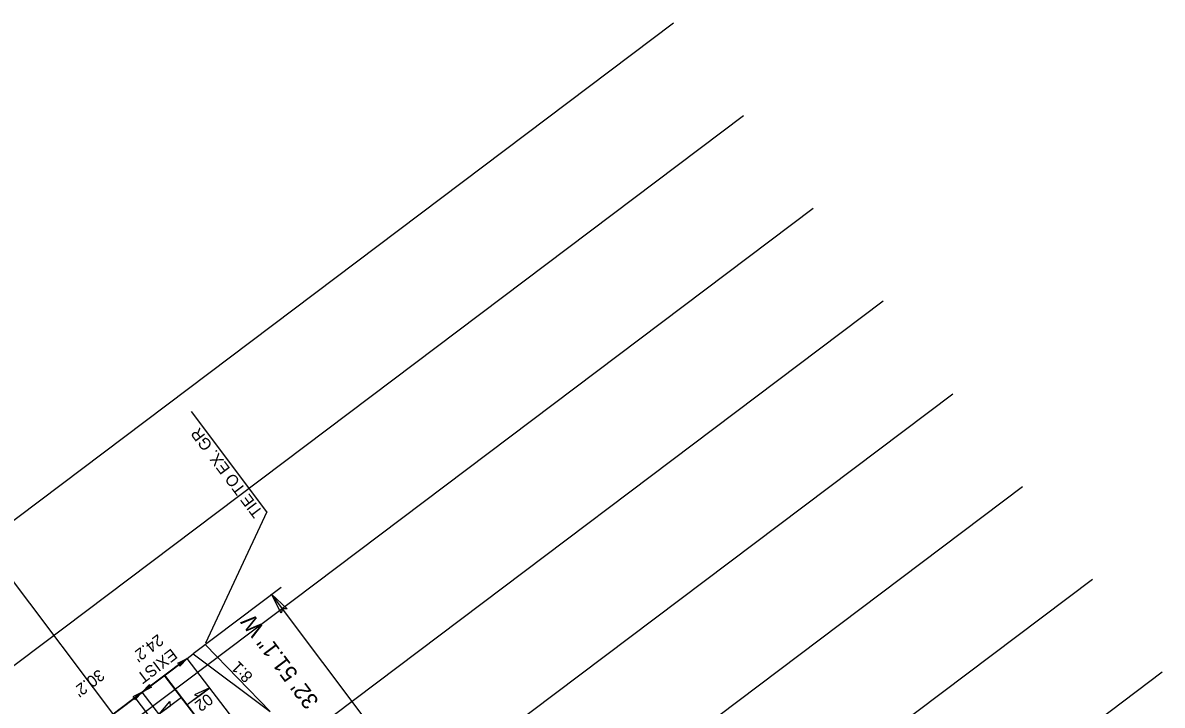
# Model space of a CAD drawing. Extents: x 1262309 to 1264352, y 775189 to 777755.
# Drawn here: x 1262668.6 to 1263159.6, y 777460.6 to 777754.5 of the extents above; entities that cross this region are included whole.
import ezdxf

# ---------------------------------------------------------------- set-up
doc = ezdxf.new("R2010")
doc.units = 0
for name, color, linetype in [('Default', 7, 'Continuous'), ('Prop Dimension', 7, 'Continuous'), ('Prop Dimension Text', 7, 'Continuous'), ('Prop EOT', 7, 'Continuous'), ('Prop Guardrail', 7, 'Continuous'), ('Prop Horizontal Alignment', 7, 'Continuous'), ('Prop Horizontal Alignment Station Label', 7, 'Continuous'), ('Prop Horizontal Alignment Tick Small', 7, 'Continuous'), ('Prop Lane Lines', 7, 'Continuous'), ('Prop Paved Shoulder', 7, 'Continuous'), ('Prop Superelevation  Arrow CELL', 7, 'Continuous'), ('Prop Superelevation Label', 7, 'Continuous'), ('Scratch_Level_3', 7, 'Continuous')]:
    doc.layers.add(name, color=color, linetype=linetype)

msp = doc.modelspace()

# ---------------------------------------------------------------- linework, layer by layer
at = {"layer": 'Default'}
msp.add_line((1262681.96, 777490.76), (1262681.96, 777490.76), dxfattribs=at)
at = {"layer": 'Prop Dimension'}
for points in [[(1262724.11, 777468.28), (1262720.06, 777466.17), (1262723.17, 777469.55), (1262723.2, 777468.56)], [(1262716.91, 777462.86), (1262720.06, 777466.17), (1262715.95, 777464.11), (1262716.89, 777463.81)]]:
    msp.add_lwpolyline(points, close=True, dxfattribs=at)
at = {"layer": 'Prop Dimension Text'}
for p, q in [((1262773.81, 777543.89), (1262741.26, 777587.1)), ((1262773.81, 777543.89), (1262747.34, 777487.25)), ((1262779.91, 777511.25), (1262742.03, 777482.72)), ((1262884.16, 777364.43), (1262775.74, 777508.38)), ((1262739.39, 777480.73), (1262720.06, 777466.17)), ((1262739.39, 777480.73), (1262720.06, 777466.17)), ((1262732.81, 777475.8), (1262739.39, 777480.73)), ((1262720.06, 777466.17), (1262695.95, 777448.02)), ((1262742.48, 777463.03), (1262748.96, 777467.91))]:
    msp.add_line(p, q, dxfattribs=at)
for points in [[(1262779.91, 777500.25), (1262775.74, 777508.38), (1262782.46, 777502.11), (1262780.49, 777502.07)], [(1262735.34, 777478.62), (1262739.39, 777480.73), (1262736.27, 777477.36), (1262736.24, 777478.34)]]:
    msp.add_lwpolyline(points, close=True, dxfattribs=at)
at = {"layer": 'Prop EOT'}
for p, q in [((1262676.05, 777433.02), (1262739.39, 777480.73)), ((1262848.98, 777337.98), (1262739.39, 777480.73)), ((1262695.94, 777448.01), (1262720.06, 777466.17)), ((1262829.84, 777323.51), (1262720.06, 777466.17))]:
    msp.add_line(p, q, dxfattribs=at)
at = {"layer": 'Prop Guardrail'}
msp.add_line((1262775.22, 777457.9), (1262747.34, 777486.63), dxfattribs=at)
at = {"layer": 'Prop Horizontal Alignment'}
for p, q in [((1263127.22, 776899.61), (1262639.84, 777546.67)), ((1262839.42, 777330.73), (1262729.72, 777473.45)), ((1262839.42, 777330.73), (1262729.72, 777473.45))]:
    msp.add_line(p, q, dxfattribs=at)
at = {"layer": 'Prop Horizontal Alignment Tick Small'}
msp.add_line((1262682.03, 777490.66), (1262678.04, 777487.65), dxfattribs=at)
at = {"layer": 'Prop Lane Lines'}
msp.add_line((1262839.35, 777330.83), (1262729.57, 777473.49), dxfattribs=at)
at = {"layer": 'Prop Paved Shoulder'}
for p, q in [((1262739.39, 777480.73), (1262742.03, 777482.72)), ((1262742.03, 777482.72), (1262775.22, 777457.9)), ((1262826.64, 777321.11), (1262716.94, 777463.83))]:
    msp.add_line(p, q, dxfattribs=at)
at = {"layer": 'Prop Superelevation  Arrow CELL'}
for points in [[(1262749.13, 777468.04), (1262742.58, 777465.11), (1262744.42, 777464.49)], [(1262727.37, 777456.66), (1262732, 777462.15), (1262732.09, 777460.21)]]:
    msp.add_lwpolyline(points, close=True, dxfattribs=at)
at = {"layer": 'Prop Superelevation Label'}
for p, q in [((1262737.91, 777479.62), (1262729.72, 777473.45)), ((1262737.03, 777463.94), (1262727.37, 777456.66)), ((1262749.13, 777468.04), (1262739.47, 777460.76))]:
    msp.add_line(p, q, dxfattribs=at)
at = {"layer": 'Scratch_Level_3'}
for p, q in [((1262453.94, 777381.61), (1262949.04, 777754.52)), ((1262484.02, 777341.67), (1262979.12, 777714.58)), ((1262514.1, 777301.73), (1263009.2, 777674.65)), ((1262544.18, 777261.79), (1263039.29, 777634.71)), ((1262574.27, 777221.85), (1263069.37, 777594.77)), ((1262604.35, 777181.92), (1263099.45, 777554.83)), ((1262634.43, 777141.98), (1263129.53, 777514.89)), ((1262664.51, 777102.04), (1263159.61, 777474.95))]:
    msp.add_line(p, q, dxfattribs=at)

# ---------------------------------------------------------------- texts
at = {"layer": 'Prop Dimension Text'}
for s, rotation, p in [('TIE TO EX. GR', 126.9874, (1262772.26, 777543.76)), ("24.2'", 217.2584, (1262726.83, 777491.43)), ('8:1', 134.6408, (1262768.06, 777473.27)), ("30.2'", 217.2584, (1262701.4, 777476.35))]:
    msp.add_text(s, height=5, rotation=rotation, dxfattribs=at).set_placement(p)
at = {"layer": 'Prop Horizontal Alignment Station Label'}
msp.add_text('N 37%%d 32\' 51.1" W', height=7, rotation=127.0213, dxfattribs=at).set_placement((1262812.18, 777441.46))
at = {"layer": 'Prop Superelevation Label'}
for s, p in [('EXIST', (1262732.68, 777485.25)), ('02', (1262748.16, 777465.94))]:
    msp.add_text(s, height=5, rotation=217.2584, dxfattribs=at).set_placement(p)

doc.saveas('drawing.dxf')
